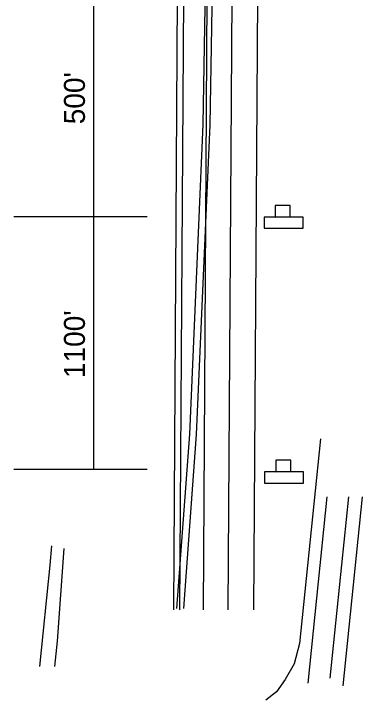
# Model space of a CAD drawing. Extents: x 612.5 to 619.9, y 600.8 to 610.9.
# Drawn here: x 615.256 to 616.254, y 602.148 to 604.113 of the extents above; entities that cross this region are included whole.
import ezdxf

# ---------------------------------------------------------------- set-up
doc = ezdxf.new("R2010")
doc.units = 0
for name, color, linetype in [('DETL-DIMS', 7, 'Continuous'), ('DETL-LINE', 7, 'Continuous'), ('DETL-NOTE', 7, 'Continuous'), ('DETL-TITL', 7, 'Continuous'), ('USER-BORD', 7, 'Continuous')]:
    doc.layers.add(name, color=color, linetype=linetype)

# ---------------------------------------------------------------- blocks, each defined once
blk = doc.blocks.new('SIGN14')
at = {"layer": 'USER-BORD'}
for points in [[(-0.0134, 0.0182), (0.011, 0.0189), (0.011, 0.0371), (-0.0134, 0.0371)], [(-0.0314, 0.0182), (-0.0314, 0), (0.032, 0), (0.032, 0.0182)]]:
    blk.add_lwpolyline(points, close=True, dxfattribs=at)

msp = doc.modelspace()

# ---------------------------------------------------------------- linework, layer by layer
at = {"layer": 'DETL-DIMS'}
for p, q in [((615.485, 602.8086), (615.485, 605.2358)), ((615.6377, 603.5315), (615.2559, 603.5315)), ((615.6377, 602.8086), (615.2559, 602.8086))]:
    msp.add_line(p, q, dxfattribs=at)
at = {"layer": 'DETL-LINE'}
for p, q in [((615.7303, 605.1667), (615.713, 602.4075)), ((615.7481, 605.1667), (615.7308, 602.4075)), ((615.8154, 605.1666), (615.7981, 602.4075)), ((615.8862, 605.1665), (615.8689, 602.4074)), ((615.9597, 605.1665), (615.9424, 602.4073))]:
    msp.add_line(p, q, dxfattribs=at)
for points in [[(615.743, 602.4107), (615.7794, 602.9085), (615.8185, 603.7952), (615.8337, 604.693), (615.8344, 605.528), (615.8187, 606.1632), (615.7799, 607.0362)], [(615.7641, 606.9234), (615.798, 606.1625), (615.8137, 605.5277), (615.813, 604.6932), (615.7977, 603.7958), (615.7587, 602.9098), (615.7222, 602.4111)], [(616.1345, 602.8968), (616.0742, 602.3111), (616.059, 602.2525), (616.0331, 602.2078), (616.0086, 602.1721), (615.9775, 602.1484)], [(616.0985, 602.1972), (616.1534, 602.7306)], [(616.2537, 602.7306), (616.1981, 602.1895)], [(615.3997, 602.5826), (615.3803, 602.3176), (615.3729, 602.2452)]]:
    msp.add_lwpolyline(points, dxfattribs=at)
at = {"layer": 'DETL-TITL'}
for points in [[(616.162, 602.2114), (616.2154, 602.7306)], [(615.3307, 602.2452), (615.3605, 602.5347), (615.3646, 602.5899)]]:
    msp.add_lwpolyline(points, dxfattribs=at)

# ---------------------------------------------------------------- block references
at = {"layer": 'DETL-LINE', "xscale": 1.7600000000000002, "yscale": 1.7600000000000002}
for p in [(616.028, 603.4988), (616.0294, 602.77)]:
    msp.add_blockref('SIGN14', p, dxfattribs=at)

# ---------------------------------------------------------------- texts
at = {"layer": 'DETL-NOTE'}
for s, p in [("500'", (615.4597, 603.7964)), ("1100'", (615.4597, 603.0702))]:
    msp.add_text(s, height=0.06, rotation=90, dxfattribs=at).set_placement(p)

doc.saveas('drawing.dxf')
